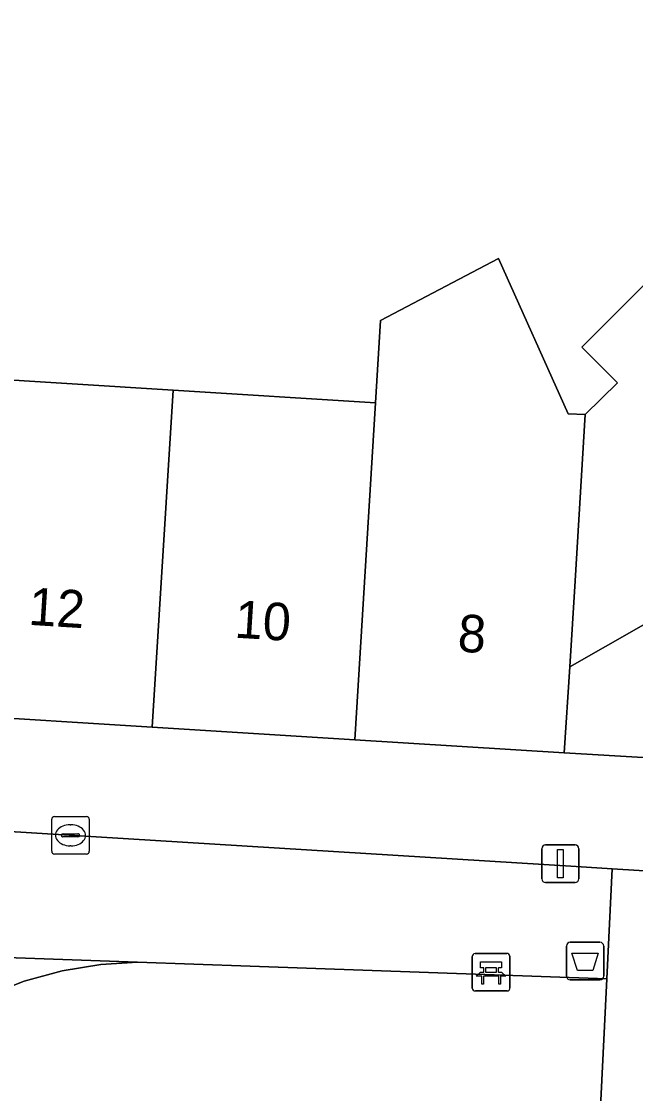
# Model space of a CAD drawing. Extents: x 160102 to 160934, y 382045 to 382923.
# Drawn here: x 160580.16 to 160596.52, y 382636.26 to 382664.84 of the extents above; entities that cross this region are included whole.
import ezdxf

# ---------------------------------------------------------------- set-up
doc = ezdxf.new("R2010")
doc.units = 0
for name, color, linetype in [('IMGEO_Afvalbak', 7, 'Continuous'), ('IMGEO_Bank', 7, 'Continuous'), ('IMGEO_Erf', 7, 'Continuous'), ('IMGEO_Groenvoorziening', 7, 'Continuous'), ('IMGEO_Kolk', 7, 'Continuous'), ('IMGEO_Lichtmast', 7, 'Continuous'), ('IMGEO_Pand', 7, 'Continuous'), ('IMGEO_Pand_nummerreeks', 7, 'Continuous'), ('IMGEO_Voetpad_open', 7, 'Continuous')]:
    doc.layers.add(name, color=color, linetype=linetype)

msp = doc.modelspace()

# ---------------------------------------------------------------- linework, layer by layer
at = {"layer": 'IMGEO_Afvalbak'}
for p, q in [((160594.779, 382640.296), (160595.569, 382640.296)), ((160595.569, 382640.296), (160594.779, 382640.296)), ((160594.679, 382639.396), (160594.679, 382640.196)), ((160594.679, 382640.196), (160594.679, 382639.396)), ((160595.669, 382640.196), (160595.669, 382639.396)), ((160595.669, 382639.396), (160595.669, 382640.196)), ((160595.569, 382639.296), (160594.779, 382639.296)), ((160594.779, 382639.296), (160595.569, 382639.296))]:
    msp.add_line(p, q, dxfattribs=at)
msp.add_lwpolyline([(160594.822, 382640.01), (160595.526, 382640.01), (160595.377, 382639.54), (160594.971, 382639.54), (160594.822, 382640.01)], dxfattribs=at)
for centre, start, end in [((160594.779, 382640.196), 90, 180), ((160594.779, 382640.196), 90, 180), ((160595.569, 382640.196), 0, 90), ((160595.569, 382640.196), 360, 90), ((160594.779, 382639.396), 180, 270), ((160594.779, 382639.396), 180, 270), ((160595.569, 382639.396), 270, 0), ((160595.569, 382639.396), 270, 0)]:
    msp.add_arc(centre, 0.1, start, end, dxfattribs=at)
at = {"layer": 'IMGEO_Bank'}
for p, q in [((160592.245, 382639.998), (160593.086, 382639.998)), ((160593.086, 382639.998), (160592.245, 382639.998)), ((160592.17, 382639.073), (160592.17, 382639.914)), ((160592.17, 382639.914), (160592.17, 382639.073)), ((160593.17, 382639.923), (160593.17, 382639.082)), ((160593.17, 382639.082), (160593.17, 382639.923)), ((160592.867, 382639.396), (160592.474, 382639.396)), ((160592.479, 382639.504), (160592.479, 382639.61)), ((160592.523, 382639.61), (160592.523, 382639.504)), ((160592.811, 382639.616), (160592.529, 382639.616)), ((160592.529, 382639.498), (160592.811, 382639.498)), ((160592.817, 382639.504), (160592.817, 382639.61)), ((160592.861, 382639.61), (160592.861, 382639.504)), ((160593.095, 382638.998), (160592.254, 382638.998)), ((160592.254, 382638.998), (160593.095, 382638.998))]:
    msp.add_line(p, q, dxfattribs=at)
for points in [[(160592.473, 382639.616), (160592.387, 382639.616), (160592.387, 382639.777), (160592.95, 382639.777), (160592.95, 382639.616), (160592.867, 382639.616)], [(160592.417, 382639.396), (160592.275, 382639.396), (160592.387, 382639.498), (160592.473, 382639.498)], [(160592.467, 382639.389), (160592.467, 382639.182), (160592.424, 382639.182), (160592.424, 382639.389)], [(160592.867, 382639.498), (160592.95, 382639.498), (160593.062, 382639.396), (160592.923, 382639.396)], [(160592.917, 382639.389), (160592.917, 382639.182), (160592.873, 382639.182), (160592.873, 382639.389)]]:
    msp.add_lwpolyline(points, dxfattribs=at)
for centre, radius, start, end in [((160592.248, 382639.92), 0.0779, 92.4484, 184.2845), ((160592.248, 382639.92), 0.0779, 92.4484, 184.2845), ((160593.092, 382639.92), 0.0779, 2.4484, 94.2845), ((160593.092, 382639.92), 0.0779, 2.4484, 94.2845), ((160592.417, 382639.389), 0.00671, 2.8957, 87.1043), ((160592.474, 382639.389), 0.00671, 92.8957, 177.1043), ((160592.472, 382639.609), 0.00671, 2.8957, 87.1043), ((160592.472, 382639.505), 0.00671, 272.8957, 357.1043), ((160592.529, 382639.609), 0.00671, 92.8957, 177.1043), ((160592.529, 382639.505), 0.00671, 182.8957, 267.1043), ((160592.811, 382639.609), 0.00671, 2.8957, 87.1043), ((160592.811, 382639.505), 0.00671, 272.8957, 357.1043), ((160592.868, 382639.609), 0.00671, 92.8957, 177.1043), ((160592.868, 382639.505), 0.00671, 182.8957, 267.1043), ((160592.866, 382639.389), 0.00671, 2.8957, 87.1043), ((160592.923, 382639.389), 0.00671, 92.8957, 177.1043), ((160592.248, 382639.076), 0.0779, 182.4484, 274.2845), ((160592.248, 382639.076), 0.0779, 182.4484, 274.2845), ((160593.092, 382639.076), 0.0779, 272.4484, 4.2845), ((160593.092, 382639.076), 0.0779, 272.4484, 4.2845)]:
    msp.add_arc(centre, radius, start, end, dxfattribs=at)
at = {"layer": 'IMGEO_Erf'}
msp.add_lwpolyline([(160573.857, 382665.884), (160573.215, 382655.694), (160578.206, 382655.383), (160578.818, 382655.345), (160584.206, 382655.009), (160589.592, 382654.673), (160589.727, 382656.867), (160592.87, 382658.516), (160594.726, 382654.382), (160595.175, 382654.357), (160596.033, 382655.208), (160595.09, 382656.16), (160599.072, 382660.142), (160602.881, 382663.95), (160606.858, 382667.926), (160611.539, 382663.245), (160615.028, 382666.729)], dxfattribs=at)
msp.add_lwpolyline([(160601.487, 382649.764), (160600.401, 382650.854), (160594.763, 382647.636), (160594.618, 382645.343), (160596.868, 382645.21)], close=True, dxfattribs=at)
at = {"layer": 'IMGEO_Groenvoorziening'}
for points in [[(160595.751, 382639.325), (160595.895, 382642.255), (160594.94, 382642.316), (160572.517, 382643.697), (160572.304, 382640.153), (160583.249, 382639.767), (160586.256, 382639.661)], [(160574.391, 382620.748), (160574.952, 382630.078), (160574.874, 382631.159), (160575.093, 382634.46), (160575.306, 382635.308), (160575.691, 382636.092), (160576.231, 382636.78), (160576.644, 382637.153), (160577.453, 382637.818), (160578.328, 382638.394), (160579.258, 382638.875), (160580.233, 382639.257), (160581.243, 382639.535), (160582.276, 382639.706), (160583.249, 382639.767), (160572.304, 382640.153), (160571.149, 382620.94)]]:
    msp.add_lwpolyline(points, close=True, dxfattribs=at)
msp.add_lwpolyline([(160579.978, 382624.096), (160581.967, 382623.615), (160583.995, 382623.344), (160586.041, 382623.287), (160587.285, 382623.409), (160588.122, 382623.714), (160588.878, 382624.187), (160589.787, 382625.163), (160591.169, 382627.872), (160592.162, 382630.942), (160592.478, 382631.541), (160592.856, 382631.979), (160593.316, 382632.329), (160594.118, 382632.656), (160595.423, 382632.661), (160595.751, 382639.325), (160586.256, 382639.661), (160583.249, 382639.767), (160582.276, 382639.706), (160581.243, 382639.535), (160580.233, 382639.257), (160579.258, 382638.875)], dxfattribs=at)
at = {"layer": 'IMGEO_Kolk'}
for p, q in [((160580.968, 382642.721), (160580.968, 382643.573)), ((160581.043, 382643.647), (160581.895, 382643.647)), ((160581.456, 382643.427), (160581.481, 382643.427)), ((160581.969, 382643.573), (160581.969, 382642.721)), ((160581.227, 382643.141), (160581.227, 382643.153)), ((160581.665, 382643.104), (160581.267, 382643.104)), ((160581.27, 382643.19), (160581.668, 382643.19)), ((160581.711, 382643.153), (160581.711, 382643.141)), ((160581.479, 382642.867), (160581.454, 382642.867)), ((160581.895, 382642.647), (160581.043, 382642.647))]:
    msp.add_line(p, q, dxfattribs=at)
for points in [[(160580.968, 382642.721), (160580.968, 382643.573)], [(160581.043, 382643.647), (160581.895, 382643.647)], [(160581.969, 382643.573), (160581.969, 382642.721)], [(160581.895, 382642.647), (160581.043, 382642.647)]]:
    msp.add_lwpolyline(points, dxfattribs=at)
for centre, radius, start, end in [((160581.045, 382643.571), 0.0765, 91.552, 178.448), ((160581.045, 382643.571), 0.0765, 91.552, 178.448), ((160581.893, 382643.571), 0.0765, 1.552, 88.448), ((160581.893, 382643.571), 0.0765, 1.552, 88.448), ((160581.267, 382643.15), 0.0403, 85.8775, 175.7526), ((160581.264, 382643.14), 0.0366, 178.938, 274.7102), ((160581.668, 382643.147), 0.043, 264.8664, 352.4533), ((160581.672, 382643.152), 0.0386, 1.7309, 96.639), ((160581.045, 382642.723), 0.0765, 181.552, 268.448), ((160581.045, 382642.723), 0.0765, 181.552, 268.448), ((160581.893, 382642.723), 0.0765, 271.552, 358.448), ((160581.893, 382642.723), 0.0765, 271.552, 358.448)]:
    msp.add_arc(centre, radius, start, end, dxfattribs=at)
for centre, major_axis, ratio, start_param, end_param in [((160581.455, 382643.147), (-0.387, 0.002), 0.722429, 4.712389, 7.853982), ((160581.48, 382643.147), (-0.39, 0.002), 0.717154, 1.570796, 4.712389)]:
    msp.add_ellipse(centre, major_axis=major_axis, ratio=ratio, start_param=start_param, end_param=end_param, dxfattribs=at)
at = {"layer": 'IMGEO_Lichtmast'}
for p, q in [((160594.12, 382642.89), (160594.91, 382642.89)), ((160594.91, 382642.89), (160594.12, 382642.89)), ((160594.02, 382641.99), (160594.02, 382642.79)), ((160594.02, 382642.79), (160594.02, 382641.99)), ((160595.01, 382642.79), (160595.01, 382641.99)), ((160595.01, 382641.99), (160595.01, 382642.79)), ((160594.91, 382641.89), (160594.12, 382641.89)), ((160594.12, 382641.89), (160594.91, 382641.89))]:
    msp.add_line(p, q, dxfattribs=at)
msp.add_lwpolyline([(160594.44, 382642.765), (160594.59, 382642.765), (160594.59, 382642.015), (160594.44, 382642.015), (160594.44, 382642.765)], dxfattribs=at)
for centre, start, end in [((160594.12, 382642.79), 90, 180), ((160594.12, 382642.79), 90, 180), ((160594.91, 382642.79), 0, 90), ((160594.91, 382642.79), 360, 90), ((160594.12, 382641.99), 180, 270), ((160594.12, 382641.99), 180, 270), ((160594.91, 382641.99), 270, 0), ((160594.91, 382641.99), 270, 0)]:
    msp.add_arc(centre, 0.1, start, end, dxfattribs=at)
at = {"layer": 'IMGEO_Pand'}
for points in [[(160605.445, 382653.722), (160599.072, 382660.142), (160595.09, 382656.16), (160596.033, 382655.208), (160595.175, 382654.357), (160594.907, 382649.929), (160594.763, 382647.636), (160600.401, 382650.854), (160601.487, 382649.764)], [(160594.907, 382649.929), (160595.175, 382654.357), (160594.726, 382654.382), (160592.87, 382658.516), (160589.727, 382656.867), (160589.592, 382654.673), (160589.039, 382645.691), (160594.618, 382645.343), (160594.763, 382647.636)], [(160578.818, 382655.345), (160578.247, 382646.363), (160583.643, 382646.027), (160584.206, 382655.009)], [(160589.039, 382645.691), (160589.592, 382654.673), (160584.206, 382655.009), (160583.643, 382646.027)]]:
    msp.add_lwpolyline(points, close=True, dxfattribs=at)
at = {"layer": 'IMGEO_Voetpad_open'}
for points in [[(160627.418, 382669.217), (160624.229, 382672.472), (160622.246, 382670.519), (160613.22, 382661.494), (160609.262, 382657.537), (160605.445, 382653.722), (160601.487, 382649.764), (160596.868, 382645.21), (160594.618, 382645.343), (160589.039, 382645.691), (160583.643, 382646.027), (160578.247, 382646.363), (160572.688, 382646.71), (160572.517, 382643.697), (160594.94, 382642.316), (160595.895, 382642.255), (160598.055, 382642.116), (160599.434, 382643.506), (160606.589, 382650.637), (160609.529, 382653.566), (160612.504, 382656.531)], [(160610.197, 382644.046), (160606.229, 382637.18), (160599.434, 382643.506), (160598.055, 382642.116), (160595.895, 382642.255), (160595.751, 382639.325), (160595.423, 382632.661), (160595.367, 382631.512), (160596.974, 382631.804)]]:
    msp.add_lwpolyline(points, dxfattribs=at)

# ---------------------------------------------------------------- texts
at = {"layer": 'IMGEO_Pand_nummerreeks'}
for s, rotation, p in [('12', 356.4331, (160580.332, 382648.758)), ('10', 356.4331, (160585.821, 382648.416)), ('8', 356.4305, (160591.762, 382648.046))]:
    msp.add_text(s, height=1, rotation=rotation, dxfattribs=at).set_placement(p)

doc.saveas('drawing.dxf')
